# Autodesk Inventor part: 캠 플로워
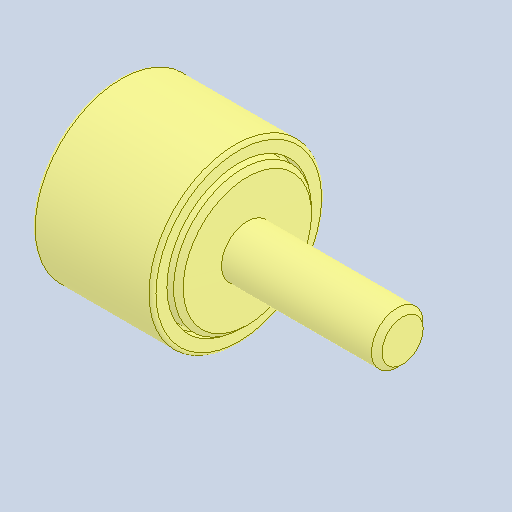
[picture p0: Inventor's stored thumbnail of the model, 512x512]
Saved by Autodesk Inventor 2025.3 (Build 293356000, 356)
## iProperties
Created: 2025-09
Part Number: 캠 플로워
Material: 일반
Description: Cam Follower with a Hexagon Socket Model CF-A-
Document SubType Name: Modeling
Designer: PC-15
Density: 1 g/cm^3
Appearance: 기본값
Company: THK
Author: jhkim
Sending System: Autodesk Inventor 2026
Preprocessor: ST-DEVELOPER v20.1
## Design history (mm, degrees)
feature "Solid1"
node "솔리드1"
